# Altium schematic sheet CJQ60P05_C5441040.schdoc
size 127 x 101 mm
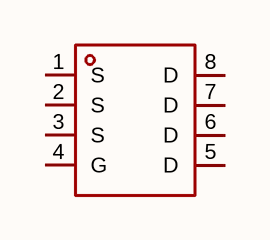
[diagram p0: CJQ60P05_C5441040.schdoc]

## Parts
Q?  cjq60p05_c5441040  [SOP-8_L4.9-W3.9-P1.27-LS6.0-BL]  (value not drawn)

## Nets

Not connected (* = marked no-connect by the designer): Q? 1(S) 2(S) 3(S) 4(G) 5(D) 6(D) 7(D) 8(D)

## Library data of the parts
Q? = cjq60p05_c5441040: 数量:1个P沟道;漏源电压(Vdss):60V;连续漏极电流(Id):5A;导通电阻(RDS(on)):61mΩ@10V;耗散功率(Pd):-;阈值电压(Vgs(th)):2V;; Manufacturer: CJ(江苏长电/长晶); AddInBom: yes; ModelId: 75c24a7891ee4dd6bdac16a7163ff87e; ModelName: SOP-8_L4.9-W3.9-P1.27-LS6.0-BL-1; ModelTransform: 192.913,236.22,0,0,0,0,-0.393,2.749,0; Number: 1个P沟道; Drain to Source Voltage: 60V; Current - Continuous Drain(Id): 5A; Gate Threshold Voltage (Vgs(th)): 2V; Gate Charge(Qg): 26nC@10V; Input Capacitance(Ciss): 2.563nF; Reverse Transfer Capacitance (Crss@Vds): 117pF; Type: P沟道; Output Capacitance(Coss): 124pF; Vgs: ±20V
